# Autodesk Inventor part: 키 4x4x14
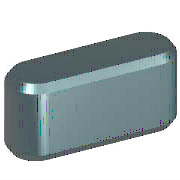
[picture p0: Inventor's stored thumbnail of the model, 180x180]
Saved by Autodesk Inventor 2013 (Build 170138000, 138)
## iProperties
Created: 2012-02
Part Number: 키 4x4x14
Material: 강철, 연강
Description: 키 및 해당 키홈
Document SubType Name: Modeling
Standard: KS B 1311
Designer: mduedu
Standards Organization: KS
Language: ko-KR
Size Designation: 4 x 4 x 14
Categories: <MemberInstance><Categories><Category DisplayName="샤프트 부품" InternalName="7f7aeb1f-a693-4053-b835-cee3144e0d98" Mnemonic="SHFT"><Category DisplayName="키" Interna
Density: 7.86 g/cm^3
Mass: 1.63695 g
Surface Area: 2.25697 cm^2
Volume: 0.208263 cm^3
IsCustomPart: 1
Author: mduedu
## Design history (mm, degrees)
workplane "Work Plane1"
workplane "Work Plane2"
sketch "스케치1"
  geometry: L1 (2, 2)-(12, 2); L2 (12, -2)-(2, -2); L3 (0, 9.4)-(0, -7.4) reference; L4 (-5, 0)-(30, 0) reference; L5 (14, 0)-(14, 7); A1 r 2 centre (2, 0) between (2, 2) and (2, -2); A2 r 2 centre (12, 0) between (12, -2) and (12, 2)
  constraints: 6 end point, 5 point on circle, 4 tangent, 3 point on line, 2 centre point, 1 horizontal, 1 parallel, 1 perpendicular
  dimensions: "d0" = 2 radius of A1 (= 0.5 x PB); "d13" = 2 radius of A2 (= 0.5 x PB); "d14" = 14 distance between parallel lines of L5 L3 (= NLG)
extrude "본체1" new body sketch "스케치1" taper "d3" = 0 deg; stored distance "d4" = 10
workplane "Work Plane3"
body "Solid1"
chamfer "모따기1" distance "d8" = 0.25 (= PHH); stored, may be unused: second distance "d9" = 0.25 (= PHH), angle "d15" = 45 deg
other parameters: "d1" = -2.5 (= -PNT), "d2" = 1.5 (= PH - PNT), "NLG" = 14 [user parameter; used in 3 equation terms], "PB" = 4 [user parameter; used in 2 equation terms], "PNT" = 2.5 [user parameter; used in 2 equation terms], "PH" = 4 [user parameter; used in 1 equation term], "PHH" = 0.25 [user parameter; used in 2 equation terms], "d10" = 0, "d16" = 0, "d17" = 0, "d18" = 0, "PLB2" = 14 (= NLG) [user parameter], "WDMAX" = 12 [user parameter], "PLB1" = 14 (= NLG) [user parameter], "RR" = 0.08 [user parameter], "PUEB" = 1.8 [user parameter]
